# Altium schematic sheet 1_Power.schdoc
size 431 x 309 mm; Symbol: Sheet-Symbol_A3; Device: Sheet-Symbol_A3; Company: 嘉立创EDA; Version: V1.0; Page Size: A3; @Project Name: 辉光管_2024.2.16; @Page Count: 3; @Update Date: 2024-07-01; @Create Date: 2024-02-16; @Schematic Name: Schematic1; @Page No: 1; @Page Name: Power
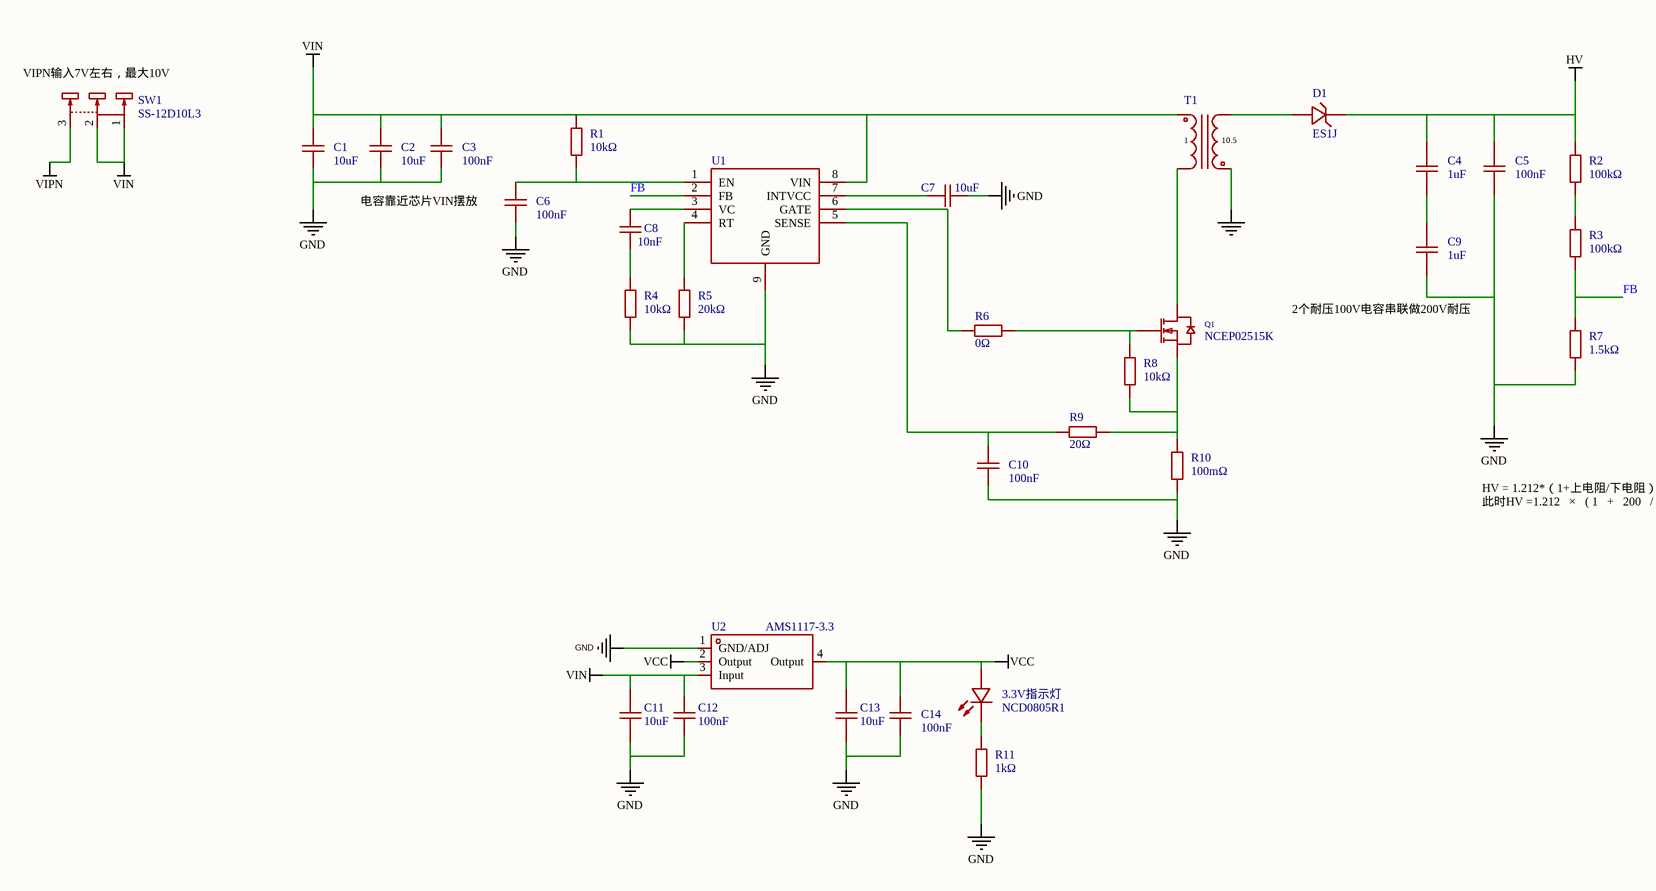
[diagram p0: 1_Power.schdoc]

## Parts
3.3V指示灯  NCD0805R1  [LED0805-R-RD]  (value not drawn)
C1  10uF  [C0805]  (value not drawn)
C2  10uF  [C0805]  (value not drawn)
C3  100nF  [C0603]  (value not drawn)
C4  1uF  [C1206]  (value not drawn)
C5  100nF  [C1206]  (value not drawn)
C6  100nF  [C0603]  (value not drawn)
C7  10uF  [C0805]  (value not drawn)
C8  10nF  [C0603]  (value not drawn)
C9  1uF  [C1206]  (value not drawn)
C10  100nF  [C0603]  (value not drawn)
C11  10uF  [C0805]  (value not drawn)
C12  100nF  [C0603]  (value not drawn)
C13  10uF  [C0805]  (value not drawn)
C14  100nF  [C0603]  (value not drawn)
D1  ES1J  [SMA_L4.4-W2.8-LS5.4-RD]  (value not drawn)
Q1  NCEP02515K  [TO-252-3_L6.6-W6.1-P4.58-LS10.1-BR-2]  (value not drawn)
R1  10kΩ  [R0603]  (value not drawn)
R2  100kΩ  [R1206]  (value not drawn)
R3  100kΩ  [R1206]  (value not drawn)
R4  10kΩ  [R0603]  (value not drawn)
R5  20kΩ  [R0603]  (value not drawn)
R6  0Ω  [R0603]  (value not drawn)
R7  1.5kΩ  [R0805]  (value not drawn)
R8  10kΩ  [R0603]  (value not drawn)
R9  20Ω  [R0603]  (value not drawn)
R10  100mΩ  [R1206]  (value not drawn)
R11  1kΩ  [R0603]  (value not drawn)
SW1  SS-12D10L3  [SW-TH_SS-12D10L3]  (value not drawn)
T1  TTRN-060S-013-T  [TTRN-060S-013]  (value not drawn)
U1  ASP3756  [ESOP-8_L4.9-W3.9-P1.27-LS6.0-BL-EP4.2]  (value not drawn)
U2  AMS1117-3.3  [SOT-223-4_L6.5-W3.5-P2.30-LS7.0-BR]  (value not drawn)

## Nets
GND: C1.1 C2.1 C3.1 C5.1 C6.1 C7.2 C9.1 C10.1 C11.1 C12.1 C13.1 C14.1 R4.1 R5.1 R7.1 R10.1 R11.1 T1.3 U1.9(GND) U2.1(GND/ADJ)
HV: C4.2 C5.2 D1.1(C) R2.1
VCC: 3.3V指示灯.1(+) C13.2 C14.2 U2.2(Output) U2.4(Output)
VIN: C1.2 C2.2 C3.2 C11.2 C12.2 R1.2 SW1.1 SW1.2 T1.1 U1.8(VIN) U2.3(Input)
VIPN: SW1.3
FB: R3.2 R7.2 U1.2(FB)
Net3.3V指示灯_2: 3.3V指示灯.2(-) R11.2
NetC4_1: C4.1 C9.2
NetC6_2: C6.2 R1.1 U1.1(EN)
NetC7_1: C7.1 U1.7(INTVCC)
NetC8_1: C8.1 R4.2
NetC8_2: C8.2 U1.3(VC)
NetC10_2: C10.2 R9.1 U1.5(SENSE)
NetD1_2: D1.2(A) T1.2
NetQ1_1: Q1.1(G) R6.2 R8.2
NetQ1_2: Q1.2(D) T1.5
NetQ1_3: Q1.3(S) R8.1 R9.2 R10.2
NetR2_2: R2.2 R3.1
NetR5_2: R5.2 U1.4(RT)
NetR6_1: R6.1 U1.6(GATE)

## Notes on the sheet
- (near SW1) VIPN输入7V左右，最大10V
- 电容靠近芯片VIN摆放
- (near C9) 2个耐压100V电容串联做200V耐压
- HV = 1.212*（1+上电阻/下电阻）
  此时HV =1.212   ×   ( 1   +   200   /   1.5 ) = 162.712

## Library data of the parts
3.3V指示灯 = NCD0805R1: 灯头类型:-;发光颜色:红色;正向电压(VF):1.6V~2.6V;功率:65mW;正向电流:20mA;主波长:615nm~630nm;二极管配置:独立二极管;透镜颜色:无色透明透镜;色温:-;发光强度:67mcd~195mcd;发光角度:130°;载带方式:-;工作温度:-30℃~+85℃;; Manufacturer: 国星光电; Symbol: FC-2012HRK-620D; Add into BOM: yes; Emitted Color: 红色; Power Dissipation: 65mW; Forward Current: 20mA; Diode Configuration: 独立二极管; Lens Color: 无色透明透镜; Viewing Angle: 130°
C1 C2 C7 = 0805X106K250NT: 容值:10uF;精度:±10%;额定电压:25V;材质(温度系数):X5R;; Manufacturer: FH(风华); Add into BOM: yes; Tolerance: ±10%; Voltage Rated: 25V; Temperature Coefficient: X5R
C3 C6 C10 C12 C14 = 0603B104K500NT: 容值:100nF;精度:±10%;额定电压:50V;材质(温度系数):X7R;; Manufacturer: FH(风华); Add into BOM: yes; Tolerance: ±10%; Voltage Rated: 50V; Temperature Coefficient: X7R
C4 C9 = CL31B105KCHNNNE: 容值:1uF;精度:±10%;额定电压:100V;材质(温度系数):X7R;; Manufacturer: SAMSUNG(三星); Add into BOM: yes; Tolerance: ±10%; Voltage Rated: 100V; Temperature Coefficient: X7R
C5 = 1206B104K251NT_C2909525: 容值:100nF;精度:±10%;额定电压:250V;材质(温度系数):X7R;; Manufacturer: FH(风华); Add into BOM: yes; Tolerance: ±10%; Voltage Rated: 250V; Temperature Coefficient: X7R
C8 = 0603B103K500NT: 容值:10nF;精度:±10%;额定电压:50V;材质(温度系数):X7R;; Manufacturer: FH(风华); Add into BOM: yes; Tolerance: ±10%; Voltage Rated: 50V; Temperature Coefficient: X7R
C11 C13 = GRM21BR61H106KE43L: 容值:10uF;精度:±10%;额定电压:50V;材质(温度系数):X5R;; Manufacturer: muRata(村田); Add into BOM: yes; Tolerance: ±10%; Voltage Rated: 50V; Temperature Coefficient: X5R
D1 = ES1J_C412438: 二极管配置:独立式;正向压降(Vf):1.7V@1A;直流反向耐压(Vr):600V;平均整流电流(Io):1A;反向恢复时间(trr):35ns;; Manufacturer: MDD; Symbol: ES1JG_C412438; Add into BOM: yes; Diode Configuration: 独立式; Reverse Voltage (Vr): 600V; Average Rectified Current (Io): 1A; Reverse Leakage Current: 5uA@600V; Reverse Recovery Time (trr): 35ns
Q1 = NCEP02515K: 类型:N沟道;漏源电压(Vdss):250V;连续漏极电流(Id):15A;功率(Pd):140W;导通电阻(RDS(on)@Vgs,Id):200mΩ@10V,15A;阈值电压(Vgs(th)@Id):3.5V@250uA;; Manufacturer: NCE(无锡新洁能); Add into BOM: yes; Type: N沟道; Drain Source Voltage (Vdss): 250V; Power Dissipation (Pd): 140W; Total Gate Charge (Qg@Vgs): 8.9nC@10V; Input Capacitance (Ciss@Vds): 475pF@125V; Reverse Transfer Capacitance (Crss@Vds): 1.2pF@125V
R1 R4 R8 = 0603WAF1002T5E: 电阻类型:厚膜电阻;阻值:10kΩ;精度:±1%;功率:100mW;; Manufacturer: UNI-ROYAL(厚声); Add into BOM: yes; Tolerance: ±1%; Power(Watts): 100mW; Temperature Coefficient: ±100ppm/℃; Overload Voltage (Max): 75V
R2 R3 = 1206W4F1003T5E: 电阻类型:厚膜电阻;阻值:100kΩ;精度:±1%;功率:250mW;最大工作电压:200V;温度系数:±100ppm/℃;; Manufacturer: UNI-ROYAL(厚声); Add into BOM: yes; Tolerance: ±1%; Power(Watts): 250mW; Overload Voltage (Max): 200V
R5 = 0603WAF2002T5E: 电阻类型:厚膜电阻;阻值:20kΩ;精度:±1%;功率:100mW;最大工作电压:75V;温度系数:±100ppm/℃;; Manufacturer: UNI-ROYAL(厚声); Add into BOM: yes; Tolerance: ±1%; Power(Watts): 100mW; Overload Voltage (Max): 75V
R6 = 0603WAF0000T5E: 电阻类型:厚膜电阻;阻值:0Ω;精度:±1%;功率:100mW;; Manufacturer: UNI-ROYAL(厚声); Add into BOM: yes; Tolerance: ±1%; Power(Watts): 100mW; Overload Voltage (Max): 75V
R7 = 0805W8F1501T5E: 电阻类型:厚膜电阻;阻值:1.5kΩ;精度:±1%;功率:125mW;最大工作电压:150V;温度系数:±100ppm/℃;; Manufacturer: UNI-ROYAL(厚声); Add into BOM: yes; Tolerance: ±1%; Power(Watts): 125mW; Overload Voltage (Max): 150V
R9 = 0603WAF200JT5E: 电阻类型:厚膜电阻;阻值:20Ω;精度:±1%;功率:100mW;最大工作电压:75V;温度系数:±100ppm/℃;; Manufacturer: UNI-ROYAL(厚声); Add into BOM: yes; Tolerance: ±1%; Power(Watts): 100mW; Overload Voltage (Max): 75V
R10 = 1206W4F100LT5E: 电阻类型:厚膜电阻;阻值:100mΩ;精度:±1%;功率:250mW;最大工作电压:200V;温度系数:±800ppm/℃;; Manufacturer: UNI-ROYAL(厚声); Add into BOM: yes; Tolerance: ±1%; Power(Watts): 250mW; Overload Voltage (Max): 200V
R11 = 0603WAF1001T5E: 电阻类型:厚膜电阻;阻值:1kΩ;精度:±1%;功率:100mW;最大工作电压:75V;温度系数:±100ppm/℃;; Manufacturer: UNI-ROYAL(厚声); Add into BOM: yes; Tolerance: ±1%; Power(Watts): 100mW; Overload Voltage (Max): 75V
SW1 = SS-12D10L3: 电路结构:单刀双掷;安装方式:直插;开关颜色:黑色;额定电流(DC):3A;额定电压(DC):125V;额定电流(AC):3A;额定电压(AC):125V;机械寿命:1万次;; Manufacturer: XKB Connectivity(中国星坤); Add into BOM: yes; Circuit: 单刀双掷; Actuator Style: 矩形柱状; Pin Style: PC引脚; Switch Length: 13mm; Switch Width: 6.8mm; Switch Height: 6.4mm; Actuator Color: 黑色; Current Rating (DC): 3A; Voltage Rating (DC): 125V; Mechanical Life: 1万次
T1 = TTRN-060S-013-T: Pin Type: IN; Add into BOM: yes
U1 = ASP3756: Add into BOM: yes
U2 = AMS1117-3.3_C369933: 输出类型:固定;最大输入电压:18V;输出电压:3.3V;最大输出电流:1A;电源纹波抑制比(PSRR):-;输出极性:正极;; Manufacturer: KEXIN(科信); Add into BOM: yes; Output Type: 固定; Maximum Input Voltage: 18V; Output Voltage: 3.3V; MAX Output Current: 1A; Dropout Voltage: 1.3V@800mA; standby current: 8mA; Output Polarity: 正极; Number of Outputs: 1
